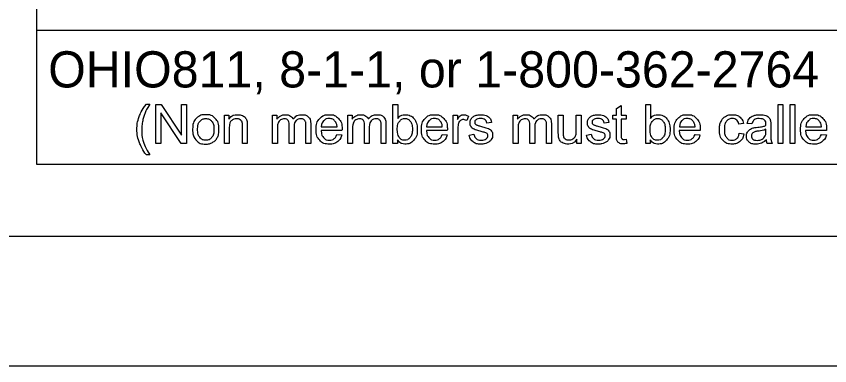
# Model space of a CAD drawing. Extents: x 0 to 39.3, y -3.9 to 22.
# Drawn here: x 3.191 to 6.342, y 0 to 1.353 of the extents above; entities that cross this region are included whole.
import ezdxf

# ---------------------------------------------------------------- set-up
doc = ezdxf.new("R2010")
doc.units = 0
for name, color, linetype in [('SH_Border', 7, 'Continuous'), ('SH_Cut_Line', 7, 'Continuous'), ('SH_Data', 7, 'Continuous'), ('SH_Text', 7, 'Continuous')]:
    doc.layers.add(name, color=color, linetype=linetype)

msp = doc.modelspace()

# ---------------------------------------------------------------- linework, layer by layer
at = {"layer": 'SH_Border'}
msp.add_lwpolyline([(1.5, 21.5), (33.5, 21.5), (33.5, 0.5), (1.5, 0.5)], close=True, dxfattribs=at)
at = {"layer": 'SH_Cut_Line'}
msp.add_lwpolyline([(0, 0), (34, 0), (34, 22), (0, 22)], close=True, dxfattribs=at)
at = {"layer": 'SH_Data'}
for p, q in [((3.2706, 0.7793), (3.2706, 3.1168)), ((7.5206, 1.2972), (3.2706, 1.2972)), ((7.5206, 0.7793), (3.2706, 0.7793))]:
    msp.add_line(p, q, dxfattribs=at)
at = {"layer": 'SH_Text'}
for points in [[(3.6953, 1.0131), (3.7084, 1.0131)], [(3.732, 0.8605), (3.732, 1.0106), (3.7523, 1.0106), (3.8313, 0.8927), (3.8313, 1.0106), (3.8503, 1.0106), (3.8503, 0.8605), (3.83, 0.8605), (3.751, 0.9784), (3.751, 0.8605), (3.732, 0.8605)], [(4.6675, 0.8605), (4.6504, 0.8605), (4.6504, 1.0106), (4.6688, 1.0106), (4.6688, 0.9571)], [(5.6465, 0.8605), (5.6295, 0.8605), (5.6295, 1.0106), (5.6479, 1.0106), (5.6479, 0.9571)], [(6.1422, 0.8605), (6.1422, 1.0106), (6.1606, 1.0106), (6.1606, 0.8605), (6.1422, 0.8605)], [(6.1888, 0.8605), (6.1888, 1.0106), (6.2072, 1.0106), (6.2072, 0.8605), (6.1888, 0.8605)], [(5.5164, 0.8923), (5.5164, 0.955), (5.5028, 0.955), (5.5028, 0.9693), (5.5164, 0.9693), (5.5164, 0.9962), (5.5348, 1.0073), (5.5348, 0.9693), (5.5533, 0.9693), (5.5533, 0.955), (5.5348, 0.955), (5.5348, 0.8912)], [(3.998, 0.8605), (3.998, 0.9693), (4.0146, 0.9693), (4.0146, 0.9538)], [(4.1844, 0.8605), (4.1844, 0.9693), (4.2009, 0.9693), (4.2009, 0.9539)], [(4.4758, 0.8605), (4.4758, 0.9693), (4.4922, 0.9693), (4.4922, 0.9539)], [(4.8835, 0.8605), (4.8835, 0.9693), (4.9001, 0.9693), (4.9001, 0.9528)], [(4.9426, 0.9658), (4.9361, 0.9488)], [(5.1168, 0.8605), (5.1168, 0.9693), (5.1332, 0.9693), (5.1332, 0.9539)], [(5.2911, 0.9019), (5.2911, 0.9693), (5.3095, 0.9693), (5.3095, 0.909)], [(5.3608, 0.911), (5.3608, 0.9693), (5.3792, 0.9693), (5.3792, 0.8605), (5.3627, 0.8605)], [(4.0164, 0.9199), (4.0164, 0.8605), (3.998, 0.8605)], [(4.0863, 0.9274), (4.0863, 0.8605), (4.0679, 0.8605), (4.0679, 0.9266)], [(4.2028, 0.9169), (4.2028, 0.8605), (4.1844, 0.8605)], [(4.2675, 0.9236), (4.2675, 0.8605), (4.249, 0.8605), (4.249, 0.9311)], [(4.3319, 0.9351), (4.3319, 0.8605), (4.3135, 0.8605), (4.3135, 0.929)], [(4.373, 0.9252), (4.4338, 0.9252)], [(4.4942, 0.9169), (4.4942, 0.8605), (4.4758, 0.8605)], [(4.5588, 0.9236), (4.5588, 0.8605), (4.5404, 0.8605), (4.5404, 0.9311)], [(4.6233, 0.9351), (4.6233, 0.8605), (4.6048, 0.8605), (4.6048, 0.929)], [(4.781, 0.9252), (4.8418, 0.9252)], [(4.902, 0.9175), (4.902, 0.8605), (4.8835, 0.8605)], [(5.0325, 0.9412), (5.0145, 0.9387)], [(5.1352, 0.9169), (5.1352, 0.8605), (5.1168, 0.8605)], [(5.1998, 0.9236), (5.1998, 0.8605), (5.1814, 0.8605), (5.1814, 0.9311)], [(5.2643, 0.9351), (5.2643, 0.8605), (5.2458, 0.8605), (5.2458, 0.929)], [(5.4871, 0.9412), (5.469, 0.9387)], [(5.7601, 0.9252), (5.8208, 0.9252)], [(6.0085, 0.9373), (5.9905, 0.9345)], [(6.041, 0.9358), (6.0229, 0.9382)], [(6.0954, 0.9083), (6.0955, 0.9151)], [(6.114, 0.9306), (6.114, 0.9061)], [(6.2496, 0.9252), (6.3104, 0.9252)], [(4.4531, 0.9101), (4.372, 0.9101)], [(4.4336, 0.8956), (4.4526, 0.8932)], [(4.8611, 0.9101), (4.78, 0.9101)], [(4.8416, 0.8956), (4.8606, 0.8932)], [(4.9461, 0.893), (4.9643, 0.8958)], [(5.4007, 0.893), (5.4189, 0.8958)], [(5.8402, 0.9101), (5.759, 0.9101)], [(5.8206, 0.8956), (5.8397, 0.8932)], [(5.9922, 0.9003), (6.0102, 0.8979)], [(6.3298, 0.9101), (6.2486, 0.9101)], [(6.3102, 0.8956), (6.3293, 0.8932)], [(4.6675, 0.8741), (4.6675, 0.8605)], [(5.3627, 0.8605), (5.3627, 0.8765)], [(5.5533, 0.8769), (5.5559, 0.8606)], [(5.6465, 0.8741), (5.6465, 0.8605)], [(6.1199, 0.8605), (6.1006, 0.8605)], [(3.7084, 0.8163), (3.6953, 0.8163)]]:
    msp.add_lwpolyline(points, dxfattribs=at)
for points, degree in [([(3.6953, 0.8163), (3.68, 0.8355), (3.6694, 0.8614), (3.6589, 0.8872), (3.6589, 0.9148), (3.6589, 0.9392), (3.6668, 0.9615), (3.676, 0.9874), (3.6953, 1.0131)], 3), ([(3.7084, 1.0131), (3.6961, 0.9918), (3.6921, 0.9827), (3.6858, 0.9686), (3.6823, 0.9532), (3.6779, 0.9341), (3.6779, 0.9147), (3.6779, 0.8655), (3.7084, 0.8163)], 3), ([(3.8745, 0.9149), (3.8745, 0.9451), (3.8913, 0.9596), (3.9053, 0.9717), (3.9255, 0.9717), (3.9479, 0.9717), (3.9621, 0.957), (3.9763, 0.9423), (3.9763, 0.9164), (3.9763, 0.8954), (3.97, 0.8834), (3.9637, 0.8714), (3.9517, 0.8647), (3.9397, 0.8581), (3.9255, 0.8581), (3.9026, 0.8581), (3.8886, 0.8727), (3.8745, 0.8873), (3.8745, 0.9149)], 3), ([(3.8935, 0.9149), (3.8935, 0.894), (3.9026, 0.8836), (3.9117, 0.8732), (3.9255, 0.8732), (3.9392, 0.8732), (3.9482, 0.8836), (3.9573, 0.8941), (3.9573, 0.9155), (3.9573, 0.9357), (3.9482, 0.9461), (3.9391, 0.9565), (3.9255, 0.9565), (3.9117, 0.9565), (3.9026, 0.9461), (3.8935, 0.9358), (3.8935, 0.9149)], 3), ([(4.0146, 0.9538), (4.0265, 0.9717), (4.0492, 0.9717), (4.059, 0.9717), (4.0672, 0.9682), (4.0755, 0.9646), (4.0796, 0.9589), (4.0837, 0.9532), (4.0853, 0.9453), (4.0863, 0.9402), (4.0863, 0.9274)], 3), ([(4.0679, 0.9266), (4.0679, 0.9379), (4.0657, 0.9434), (4.0636, 0.949), (4.0581, 0.9524), (4.0526, 0.9557), (4.0453, 0.9557), (4.0335, 0.9557), (4.0249, 0.9482), (4.0164, 0.9407), (4.0164, 0.9199)], 3), ([(4.2009, 0.9539), (4.206, 0.962), (4.2145, 0.9668), (4.223, 0.9717), (4.2339, 0.9717), (4.2459, 0.9717), (4.2537, 0.9667), (4.2614, 0.9616), (4.2646, 0.9526), (4.2775, 0.9717), (4.2982, 0.9717), (4.3145, 0.9717), (4.3232, 0.9627), (4.3319, 0.9538), (4.3319, 0.9351)], 3), ([(4.249, 0.9311), (4.249, 0.9434), (4.2445, 0.9495), (4.24, 0.9557), (4.2298, 0.9557), (4.222, 0.9557), (4.2154, 0.9516), (4.2088, 0.9475), (4.2058, 0.9396), (4.2028, 0.9317), (4.2028, 0.9169)], 3), ([(4.3135, 0.929), (4.3135, 0.94), (4.3117, 0.9449), (4.3099, 0.9497), (4.3052, 0.9527), (4.3005, 0.9557), (4.2941, 0.9557), (4.2826, 0.9557), (4.275, 0.9481), (4.2675, 0.9404), (4.2675, 0.9236)], 3), ([(4.4526, 0.8932), (4.4481, 0.8765), (4.4359, 0.8673), (4.4237, 0.8581), (4.4048, 0.8581), (4.3809, 0.8581), (4.367, 0.8728), (4.353, 0.8874), (4.353, 0.914), (4.353, 0.9414), (4.3671, 0.9566), (4.3812, 0.9717), (4.4038, 0.9717), (4.4256, 0.9717), (4.4394, 0.9569), (4.4532, 0.942), (4.4532, 0.9151), (4.4532, 0.9134), (4.4531, 0.9101)], 3), ([(4.4338, 0.9252), (4.4325, 0.939), (4.4268, 0.9459), (4.418, 0.9566), (4.404, 0.9566), (4.3912, 0.9566), (4.3826, 0.9481), (4.3739, 0.9395), (4.373, 0.9252)], 3), ([(4.4922, 0.9539), (4.4974, 0.962), (4.5059, 0.9668), (4.5144, 0.9717), (4.5252, 0.9717), (4.5373, 0.9717), (4.5451, 0.9667), (4.5528, 0.9616), (4.556, 0.9526), (4.5689, 0.9717), (4.5896, 0.9717), (4.6058, 0.9717), (4.6146, 0.9627), (4.6233, 0.9538), (4.6233, 0.9351)], 3), ([(4.5404, 0.9311), (4.5404, 0.9434), (4.5359, 0.9495), (4.5314, 0.9557), (4.5211, 0.9557), (4.5133, 0.9557), (4.5067, 0.9516), (4.5001, 0.9475), (4.4972, 0.9396), (4.4942, 0.9317), (4.4942, 0.9169)], 3), ([(4.6048, 0.929), (4.6048, 0.94), (4.6031, 0.9449), (4.6013, 0.9497), (4.5965, 0.9527), (4.5918, 0.9557), (4.5855, 0.9557), (4.574, 0.9557), (4.5664, 0.9481), (4.5588, 0.9404), (4.5588, 0.9236)], 3), ([(4.6672, 0.9157), (4.6672, 0.8961), (4.6726, 0.8874), (4.6812, 0.8732), (4.6961, 0.8732), (4.7081, 0.8732), (4.7169, 0.8837), (4.7257, 0.8942), (4.7257, 0.915), (4.7257, 0.9363), (4.7173, 0.9465), (4.7088, 0.9566), (4.6969, 0.9566), (4.6848, 0.9566), (4.676, 0.9461), (4.6672, 0.9356), (4.6672, 0.9157)], 3), ([(4.6688, 0.9571), (4.6805, 0.9717), (4.6986, 0.9717), (4.7087, 0.9717), (4.7176, 0.9677), (4.7266, 0.9636), (4.7324, 0.9563), (4.7382, 0.949), (4.7414, 0.9386), (4.7447, 0.9283), (4.7447, 0.9165), (4.7447, 0.8886), (4.7309, 0.8733), (4.7171, 0.8581), (4.6977, 0.8581), (4.6784, 0.8581), (4.6675, 0.8741)], 3), ([(4.8606, 0.8932), (4.8561, 0.8765), (4.8439, 0.8673), (4.8317, 0.8581), (4.8128, 0.8581), (4.7889, 0.8581), (4.7749, 0.8728), (4.761, 0.8874), (4.761, 0.914), (4.761, 0.9414), (4.7751, 0.9566), (4.7892, 0.9717), (4.8118, 0.9717), (4.8336, 0.9717), (4.8474, 0.9569), (4.8612, 0.942), (4.8612, 0.9151), (4.8612, 0.9134), (4.8611, 0.9101)], 3), ([(4.8418, 0.9252), (4.8405, 0.939), (4.8348, 0.9459), (4.826, 0.9566), (4.8119, 0.9566), (4.7992, 0.9566), (4.7906, 0.9481), (4.7819, 0.9395), (4.781, 0.9252)], 3), ([(4.9001, 0.9528), (4.9065, 0.9644), (4.9118, 0.968), (4.9172, 0.9717), (4.9237, 0.9717), (4.933, 0.9717), (4.9426, 0.9658)], 3), ([(4.9361, 0.9488), (4.9294, 0.9527), (4.9227, 0.9527), (4.9167, 0.9527), (4.9119, 0.9491), (4.9071, 0.9454), (4.905, 0.939), (4.902, 0.9291), (4.902, 0.9175)], 3), ([(5.0145, 0.9387), (5.0132, 0.9472), (5.0073, 0.9519), (5.0014, 0.9566), (4.9907, 0.9566), (4.9779, 0.9566), (4.9725, 0.9524), (4.9671, 0.9482), (4.9671, 0.9425), (4.9671, 0.939), (4.9693, 0.9361), (4.9716, 0.9331), (4.9764, 0.9312), (4.9792, 0.9301), (4.9927, 0.9264), (5.0123, 0.9212), (5.0201, 0.9179), (5.0278, 0.9146), (5.0322, 0.9082), (5.0367, 0.9019), (5.0367, 0.8925), (5.0367, 0.8832), (5.0313, 0.8751), (5.0259, 0.867), (5.0157, 0.8625), (5.0056, 0.8581), (4.9927, 0.8581), (4.9715, 0.8581), (4.9604, 0.8669), (4.9492, 0.8757), (4.9461, 0.893)], 3), ([(4.9643, 0.8958), (4.9659, 0.8849), (4.9729, 0.879), (4.98, 0.8732), (4.9926, 0.8732), (5.0053, 0.8732), (5.0115, 0.8784), (5.0177, 0.8835), (5.0177, 0.8905), (5.0177, 0.8968), (5.0122, 0.9004), (5.0084, 0.9028), (4.9933, 0.9066), (4.973, 0.9117), (4.9652, 0.9155), (4.9573, 0.9192), (4.9533, 0.9258), (4.9492, 0.9324), (4.9492, 0.9404), (4.9492, 0.9477), (4.9526, 0.9538), (4.9559, 0.96), (4.9616, 0.9641), (4.966, 0.9673), (4.9734, 0.9695), (4.9808, 0.9717), (4.9893, 0.9717), (5.0022, 0.9717), (5.0119, 0.968), (5.0216, 0.9643), (5.0262, 0.958), (5.0308, 0.9517), (5.0325, 0.9412)], 3), ([(5.1332, 0.9539), (5.1384, 0.962), (5.1469, 0.9668), (5.1554, 0.9717), (5.1662, 0.9717), (5.1783, 0.9717), (5.1861, 0.9667), (5.1938, 0.9616), (5.197, 0.9526), (5.2099, 0.9717), (5.2306, 0.9717), (5.2468, 0.9717), (5.2555, 0.9627), (5.2643, 0.9538), (5.2643, 0.9351)], 3), ([(5.1814, 0.9311), (5.1814, 0.9434), (5.1769, 0.9495), (5.1724, 0.9557), (5.1621, 0.9557), (5.1543, 0.9557), (5.1477, 0.9516), (5.1411, 0.9475), (5.1381, 0.9396), (5.1352, 0.9317), (5.1352, 0.9169)], 3), ([(5.2458, 0.929), (5.2458, 0.94), (5.2441, 0.9449), (5.2423, 0.9497), (5.2375, 0.9527), (5.2328, 0.9557), (5.2265, 0.9557), (5.215, 0.9557), (5.2074, 0.9481), (5.1998, 0.9404), (5.1998, 0.9236)], 3), ([(5.469, 0.9387), (5.4678, 0.9472), (5.4619, 0.9519), (5.456, 0.9566), (5.4452, 0.9566), (5.4325, 0.9566), (5.4271, 0.9524), (5.4216, 0.9482), (5.4216, 0.9425), (5.4216, 0.939), (5.4239, 0.9361), (5.4262, 0.9331), (5.431, 0.9312), (5.4337, 0.9301), (5.4473, 0.9264), (5.4669, 0.9212), (5.4746, 0.9179), (5.4824, 0.9146), (5.4868, 0.9082), (5.4912, 0.9019), (5.4912, 0.8925), (5.4912, 0.8832), (5.4858, 0.8751), (5.4805, 0.867), (5.4703, 0.8625), (5.4601, 0.8581), (5.4473, 0.8581), (5.4261, 0.8581), (5.4149, 0.8669), (5.4038, 0.8757), (5.4007, 0.893)], 3), ([(5.4189, 0.8958), (5.4204, 0.8849), (5.4275, 0.879), (5.4345, 0.8732), (5.4472, 0.8732), (5.4599, 0.8732), (5.4661, 0.8784), (5.4722, 0.8835), (5.4722, 0.8905), (5.4722, 0.8968), (5.4668, 0.9004), (5.463, 0.9028), (5.4479, 0.9066), (5.4276, 0.9117), (5.4197, 0.9155), (5.4119, 0.9192), (5.4078, 0.9258), (5.4038, 0.9324), (5.4038, 0.9404), (5.4038, 0.9477), (5.4071, 0.9538), (5.4105, 0.96), (5.4162, 0.9641), (5.4205, 0.9673), (5.428, 0.9695), (5.4354, 0.9717), (5.4439, 0.9717), (5.4567, 0.9717), (5.4664, 0.968), (5.4761, 0.9643), (5.4807, 0.958), (5.4854, 0.9517), (5.4871, 0.9412)], 3), ([(5.6463, 0.9157), (5.6463, 0.8961), (5.6516, 0.8874), (5.6603, 0.8732), (5.6751, 0.8732), (5.6872, 0.8732), (5.696, 0.8837), (5.7048, 0.8942), (5.7048, 0.915), (5.7048, 0.9363), (5.6963, 0.9465), (5.6879, 0.9566), (5.676, 0.9566), (5.6639, 0.9566), (5.6551, 0.9461), (5.6463, 0.9356), (5.6463, 0.9157)], 3), ([(5.6479, 0.9571), (5.6596, 0.9717), (5.6777, 0.9717), (5.6877, 0.9717), (5.6967, 0.9677), (5.7057, 0.9636), (5.7114, 0.9563), (5.7172, 0.949), (5.7205, 0.9386), (5.7238, 0.9283), (5.7238, 0.9165), (5.7238, 0.8886), (5.7099, 0.8733), (5.6961, 0.8581), (5.6768, 0.8581), (5.6575, 0.8581), (5.6465, 0.8741)], 3), ([(5.8397, 0.8932), (5.8352, 0.8765), (5.823, 0.8673), (5.8108, 0.8581), (5.7918, 0.8581), (5.768, 0.8581), (5.754, 0.8728), (5.74, 0.8874), (5.74, 0.914), (5.74, 0.9414), (5.7542, 0.9566), (5.7683, 0.9717), (5.7908, 0.9717), (5.8126, 0.9717), (5.8265, 0.9569), (5.8403, 0.942), (5.8403, 0.9151), (5.8403, 0.9134), (5.8402, 0.9101)], 3), ([(5.8208, 0.9252), (5.8196, 0.939), (5.8139, 0.9459), (5.805, 0.9566), (5.791, 0.9566), (5.7783, 0.9566), (5.7696, 0.9481), (5.761, 0.9395), (5.7601, 0.9252)], 3), ([(6.0102, 0.8979), (6.0073, 0.8792), (5.995, 0.8686), (5.9828, 0.8581), (5.965, 0.8581), (5.9426, 0.8581), (5.929, 0.8727), (5.9155, 0.8872), (5.9155, 0.9145), (5.9155, 0.9321), (5.9213, 0.9453), (5.9272, 0.9585), (5.9391, 0.9651), (5.951, 0.9717), (5.9651, 0.9717), (5.9828, 0.9717), (5.9941, 0.9627), (6.0053, 0.9538), (6.0085, 0.9373)], 3), ([(5.9905, 0.9345), (5.988, 0.9455), (5.9815, 0.9511), (5.975, 0.9566), (5.9658, 0.9566), (5.9519, 0.9566), (5.9432, 0.9466), (5.9345, 0.9366), (5.9345, 0.915), (5.9345, 0.8931), (5.9429, 0.8831), (5.9513, 0.8732), (5.9648, 0.8732), (5.9757, 0.8732), (5.9829, 0.8798), (5.9902, 0.8865), (5.9922, 0.9003)], 3), ([(6.097, 0.8739), (6.0867, 0.8652), (6.0772, 0.8616), (6.0678, 0.8581), (6.0569, 0.8581), (6.039, 0.8581), (6.0294, 0.8668), (6.0197, 0.8756), (6.0197, 0.8892), (6.0197, 0.8971), (6.0234, 0.9037), (6.027, 0.9103), (6.0329, 0.9143), (6.0388, 0.9183), (6.0461, 0.9204), (6.0516, 0.9218), (6.0625, 0.9231), (6.0848, 0.9258), (6.0954, 0.9295), (6.0955, 0.9333), (6.0955, 0.9343), (6.0955, 0.9456), (6.0903, 0.9502), (6.0832, 0.9565), (6.0693, 0.9565), (6.0563, 0.9565), (6.0502, 0.9519), (6.044, 0.9474), (6.041, 0.9358)], 3), ([(6.0229, 0.9382), (6.0254, 0.9498), (6.031, 0.9569), (6.0367, 0.964), (6.0473, 0.9679), (6.0579, 0.9717), (6.072, 0.9717), (6.0859, 0.9717), (6.0946, 0.9684), (6.1033, 0.9651), (6.1074, 0.9602), (6.1115, 0.9552), (6.1131, 0.9476), (6.114, 0.9429), (6.114, 0.9306)], 3), ([(6.3293, 0.8932), (6.3248, 0.8765), (6.3126, 0.8673), (6.3004, 0.8581), (6.2814, 0.8581), (6.2576, 0.8581), (6.2436, 0.8728), (6.2296, 0.8874), (6.2296, 0.914), (6.2296, 0.9414), (6.2438, 0.9566), (6.2579, 0.9717), (6.2804, 0.9717), (6.3022, 0.9717), (6.316, 0.9569), (6.3299, 0.942), (6.3299, 0.9151), (6.3299, 0.9134), (6.3298, 0.9101)], 3), ([(6.3104, 0.9252), (6.3092, 0.939), (6.3034, 0.9459), (6.2946, 0.9566), (6.2806, 0.9566), (6.2679, 0.9566), (6.2592, 0.9481), (6.2506, 0.9395), (6.2496, 0.9252)], 3), ([(6.0955, 0.9151), (6.0854, 0.911), (6.0654, 0.9081), (6.054, 0.9065), (6.0493, 0.9044), (6.0445, 0.9024), (6.042, 0.8984), (6.0394, 0.8945), (6.0394, 0.8897), (6.0394, 0.8823), (6.045, 0.8774), (6.0506, 0.8725), (6.0613, 0.8725), (6.072, 0.8725), (6.0802, 0.8771), (6.0885, 0.8818), (6.0924, 0.8899), (6.0954, 0.8961), (6.0954, 0.9083)], 3), ([(4.372, 0.9101), (4.373, 0.8922), (4.3821, 0.8827), (4.3912, 0.8732), (4.4049, 0.8732), (4.415, 0.8732), (4.4222, 0.8785), (4.4294, 0.8839), (4.4336, 0.8956)], 3), ([(4.78, 0.9101), (4.781, 0.8922), (4.7901, 0.8827), (4.7992, 0.8732), (4.8129, 0.8732), (4.823, 0.8732), (4.8302, 0.8785), (4.8374, 0.8839), (4.8416, 0.8956)], 3), ([(5.3627, 0.8765), (5.35, 0.8581), (5.3282, 0.8581), (5.3186, 0.8581), (5.3103, 0.8618), (5.3019, 0.8654), (5.2979, 0.871), (5.2938, 0.8766), (5.2922, 0.8847), (5.2911, 0.8901), (5.2911, 0.9019)], 3), ([(5.3095, 0.909), (5.3095, 0.8946), (5.3106, 0.8895), (5.3124, 0.8823), (5.318, 0.8781), (5.3236, 0.874), (5.3319, 0.874), (5.3402, 0.874), (5.3475, 0.8782), (5.3547, 0.8825), (5.3577, 0.8898), (5.3608, 0.8971), (5.3608, 0.911)], 3), ([(5.5559, 0.8606), (5.5481, 0.859), (5.542, 0.859), (5.532, 0.859), (5.5264, 0.8622), (5.5209, 0.8653), (5.5187, 0.8705), (5.5164, 0.8757), (5.5164, 0.8923)], 3), ([(5.5348, 0.8912), (5.5348, 0.8833), (5.5358, 0.8811), (5.5368, 0.8788), (5.539, 0.8775), (5.5411, 0.8761), (5.5452, 0.8761), (5.5483, 0.8761), (5.5533, 0.8769)], 3), ([(5.759, 0.9101), (5.7601, 0.8922), (5.7692, 0.8827), (5.7783, 0.8732), (5.7919, 0.8732), (5.8021, 0.8732), (5.8092, 0.8785), (5.8164, 0.8839), (5.8206, 0.8956)], 3), ([(6.114, 0.9061), (6.114, 0.8804), (6.1152, 0.8735), (6.1164, 0.8667), (6.1199, 0.8605)], 3), ([(6.2486, 0.9101), (6.2496, 0.8922), (6.2588, 0.8827), (6.2679, 0.8732), (6.2815, 0.8732), (6.2917, 0.8732), (6.2988, 0.8785), (6.306, 0.8839), (6.3102, 0.8956)], 3), ([(6.1006, 0.8605), (6.0978, 0.8662), (6.097, 0.8739)], 2)]:
    msp.add_open_spline(points, degree=degree, dxfattribs=at)

# ---------------------------------------------------------------- texts
msp.add_text('OHIO811, 8-1-1, or 1-800-362-2764', height=0.14, dxfattribs=at).set_placement((3.3151, 1.0772))

doc.saveas('drawing.dxf')
